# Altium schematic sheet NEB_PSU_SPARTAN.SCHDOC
size A4; Organization: Altium Limited; Address1: L3, 12a Rodborough Rd; Address2: Frenchs Forest; Address3: NSW; Address4: Australia 2086; DocumentNumber: 7; SheetNumber: 7; SheetTotal: 10
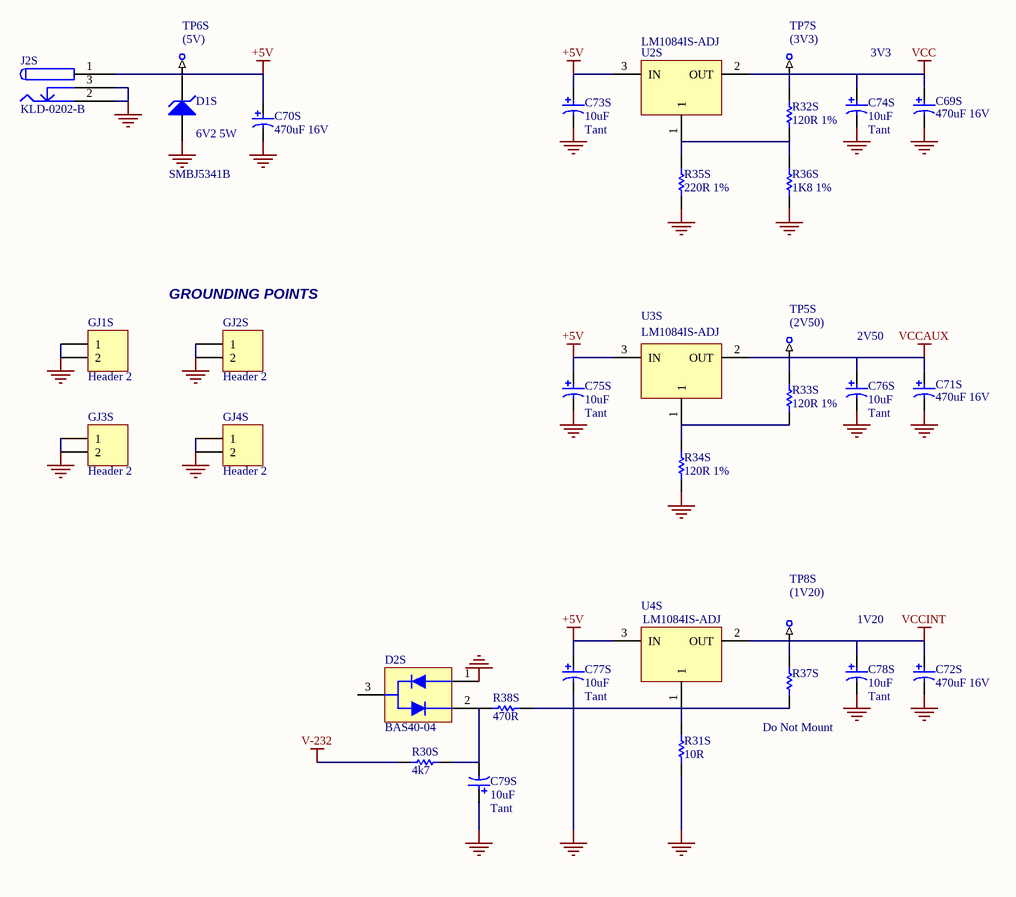
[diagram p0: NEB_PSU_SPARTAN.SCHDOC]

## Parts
C69S  470uF 16V  [RB8/3.5]
C70S  470uF 16V  [RB8/3.5]
C71S  470uF 16V  [RB8/3.5]
C72S  470uF 16V  [RB8/3.5]
C73S  10uF  Capacitor Type: Tant  [MCCT-B]
C74S  10uF  Capacitor Type: Tant  [MCCT-B]
C75S  10uF  Capacitor Type: Tant  [MCCT-B]
C76S  10uF  Capacitor Type: Tant  [MCCT-B]
C77S  10uF  Capacitor Type: Tant  [MCCT-B]
C78S  10uF  Capacitor Type: Tant  [MCCT-B]
C79S  10uF  Capacitor Type: Tant  [MCCT-B]
D1S  SMBJ5341B  Part Description: 6V2 5W  [DO214]
D2S  BAS40-04  [SO-G3]
GJ1S  Header 2  [HDR1X2]
GJ2S  Header 2  [HDR1X2]
GJ3S  Header 2  [HDR1X2]
GJ4S  Header 2  [HDR1X2]
J2S  KLD-0202-B  [KLD-0202]
R30S  4k7  [CR2012-0805]
R31S  10R  [CR2012-0805]
R32S  120R 1%  [CR2012-0805]
R33S  120R 1%  [CR2012-0805]
R34S  120R 1%  [CR2012-0805]
R35S  220R 1%  [CR2012-0805]
R36S  1K8 1%  [CR2012-0805]
R37S  Do Not Mount  [CR2012-0805]
R38S  470R  [CR2012-0805]
TP5S  (2V50)  [TestPin]  (no BOM)
TP6S  (5V)  [TestPin]  (no BOM)
TP7S  (3V3)  [TestPin]  (no BOM)
TP8S  (1V20)  [TestPin]  (no BOM)
U2S  LM1084IS-ADJ  [TO-263]
U3S  LM1084IS-ADJ  [TO-263]
U4S  LM1084IS-ADJ  [TO-263]

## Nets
+5V: C70S.1 C73S.1 C75S.1 C77S.1 D1S.2(K) J2S.1 J2S.1A J2S.1B TP6S.1 U2S.3(IN) U3S.3(IN) U4S.3(IN)
GND: C69S.2 C70S.2 C71S.2 C72S.2 C73S.2 C74S.2 C75S.2 C76S.2 C77S.2 C78S.2 C79S.1 D1S.1(A) D2S.1 GJ1S.1 GJ1S.2 GJ2S.1 GJ2S.2 GJ3S.1 GJ3S.2 GJ4S.1 GJ4S.2 J2S.2 J2S.2A J2S.2B J2S.3 J2S.3A J2S.3B R31S.1 R34S.1 R35S.1 R36S.1
V-232: R30S.2
VCC: C69S.1 C74S.1 R32S.2 TP7S.1 U2S.2(OUT) U2S.4(HeatSink)
VCCAUX: C71S.1 C76S.1 R33S.2 TP5S.1 U3S.2(OUT) U3S.4(HeatSink)
VCCINT: C72S.1 C78S.1 R37S.2 TP8S.1 U4S.2(OUT) U4S.4(HeatSink)
NetC79S_2: C79S.2 D2S.2 R30S.1 R38S.2
NetR31S_2: R31S.2 R37S.1 R38S.1 U4S.1
NetR32S_1: R32S.1 R35S.2 R36S.2 U2S.1
NetR33S_1: R33S.1 R34S.2 U3S.1

Not connected (* = marked no-connect by the designer): D2S 3

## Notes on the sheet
- 3V3
- (near GJ2S) GROUNDING POINTS
- 2V50
- 1V20

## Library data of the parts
C69S C70S C71S C72S C73S C74S C75S C76S C77S C78S C79S = CAP_POLAR: Polar Capacitor; Fitted: True
D1S = BZG03C13: Zener Diode, 6.2V, 5W; Manufacturer: Microsemi; Fitted: True
D2S = BAS40-04: Shottky Diode Pair; Fitted: True
GJ1S GJ2S GJ3S GJ4S = Header 2: Header, 2-Pin; Manufacturer: Generic Components; Class I: Connector; Fitted: True
J2S = KLD-0202-B: Low Voltage Power Supply Connector; Manufacturer: Kycon; Fitted: True
R30S R31S R32S R33S R34S R35S R36S R37S R38S = RES: Resistor; Fitted: True
TP5S TP6S TP7S TP8S = TestPin
U2S U3S U4S = LM1084IS-ADJ: 5A Low Dropout Positive Regulators; Manufacturer: National Semi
